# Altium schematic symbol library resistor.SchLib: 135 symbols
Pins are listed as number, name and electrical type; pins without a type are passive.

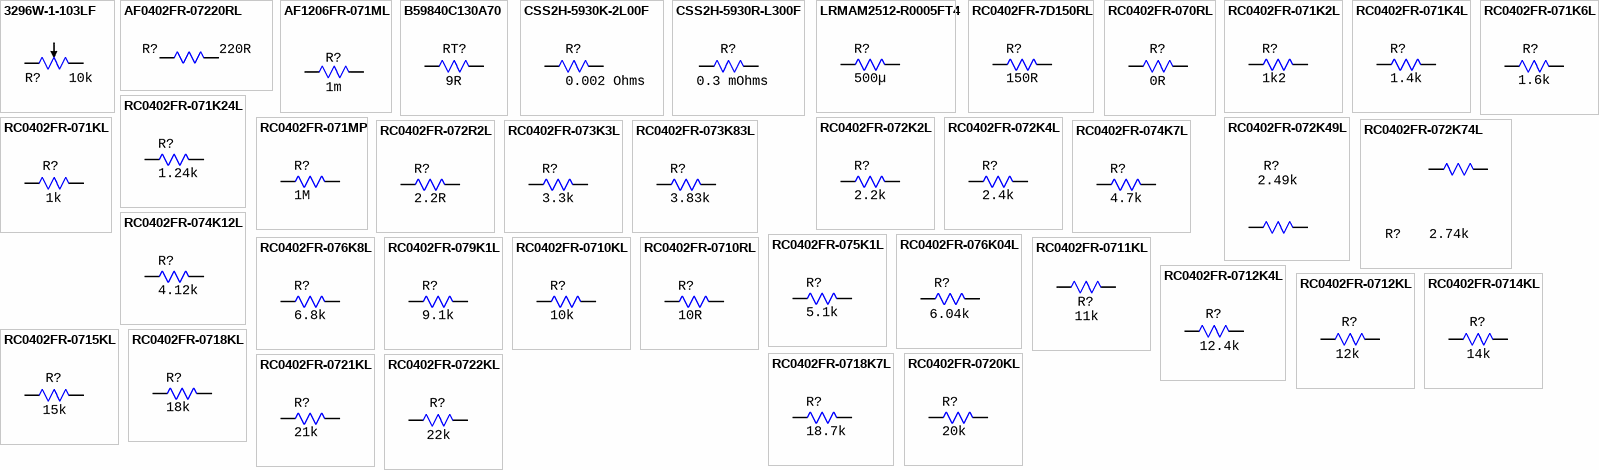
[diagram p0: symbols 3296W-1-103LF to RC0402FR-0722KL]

## 3296W-1-103LF
designator R?  value 10k  (hidden comment: 3296W-1-103LF)
10 kOhms, trimmer, ±10%, 0.5W, -55...+150°C; Manufacturer: Bourns
footprint RES: 3296W
pins: 1, 2, 3

## AF0402FR-07220RL
designator R?  value 220R  (hidden comment: AF0402FR-07220RL)
220 Ohms, 0402, ±1%, 0.062W, -55...+155°C; Manufacturer: YAGEO
footprint RES: 0402
pins: 1, 2

## AF1206FR-071ML
designator R?  value 1m  (hidden comment: AF1206FR-071ML)
1 mOhm, 1206, ±1%, 0.25W, -55...+155°C; Manufacturer: YAGEO
footprint RES: 1206
pins: 1, 2

## B59840C130A70
designator RT?  value 9R  (hidden comment: B59840C130A70)
9 Ohm, 13.5W, 500mA, 265V, D13.5W5H17, -55...+155°C; Manufacturer: Epcos; Manufacturer: TDK EPCOS
footprint RES: B59840C0130A070 (NTC)
pins: 1, 2

## CSS2H-5930K-2L00F
designator R?  value 0.002 Ohms  (hidden comment: CSS2H-5930K-2L00F)
0.002 Ohms, 2512, ±1%, 7W, -55...+170°C; Manufacturer: Bourns
footprint RES: CSS2H (2512)
pins: 1, 2

## CSS2H-5930R-L300F
designator R?  value 0.3 mOhms  (hidden comment: CSS2H-5930R-L300F)
0.0003 Ohms, 2512, ±1%, 10W, -55...+170°C; Manufacturer: Bourns
footprint RES: CSS2H (2512)
pins: 1, 2

## LRMAM2512-R0005FT4
designator R?  value 500µ  (hidden comment: LRMAM2512-R0005FT4)
0.5 mOhms, 2512, ±1%, 2W, -55...+170°C; Manufacturer: Welwyn; Manufacturer: TT Welwyn
footprint RES: CSS2H (2512)
pins: 1, 2

## RC0402FR-7D150RL
designator R?  value 150R  (hidden comment: RC0402FR-7D150RL)
150 Ohms, 0402, ±1%, 0.062W, -55...+155°C; Manufacturer: YAGEO
footprint RES: 0402
pins: 1, 2

## RC0402FR-070RL
designator R?  value 0R  (hidden comment: RC0402FR-070RL)
0 Ohms, 0402, ±1%, 0.062W, -55...+155°C; Manufacturer: Yageo
footprint RES: 0402
pins: 1, 2

## RC0402FR-071K2L
designator R?  value 1k2  (hidden comment: RC0402FR-071K2L)
1.2 kOhm, 0402, ±1%, 0.062W, -55...+155°C; Manufacturer: Yageo
footprint RES: 0402
pins: 1, 2

## RC0402FR-071K4L
designator R?  value 1.4k  (hidden comment: RC0402FR-071K4L)
1.4 kOhm, 0402, ±1%, 0.062W, -55...+155°C; Manufacturer: Yageo
footprint RES: 0402
pins: 1, 2

## RC0402FR-071K6L
designator R?  value 1.6k  (hidden comment: RC0402FR-071K6L)
1.6 kOhms, 0402, ±1%, 0.062W, -55...+155°C; Manufacturer: Yageo
footprint RES: 0402
pins: 1, 2

## RC0402FR-071K24L
designator R?  value 1.24k  (hidden comment: RC0402FR-071K24L)
1.24 kOhm, 0402, ±1%, 0.062W, -55...+155°C; Manufacturer: Yageo
footprint RES: 0402
pins: 1, 2

## RC0402FR-071KL
designator R?  value 1k  (hidden comment: RC0402FR-071KL)
1 kOhm, 0402, ±1%, 0.062W, -55...+155°C; Manufacturer: Yageo
footprint RES: 0402
pins: 1, 2

## RC0402FR-071MP
designator R?  value 1M  (hidden comment: RC0402FR-071MP)
1 MOhms, 0402, ±1%, 0.062W, -55...+155°C; Manufacturer: Yageo; PartNumber: RC0402FR-0793K1L
footprint RES: 0402
pins: 1, 2

## RC0402FR-072K2L
designator R?  value 2.2k  (hidden comment: RC0402FR-072K2L)
2.2 kOhm, 0402, ±1%, 0.062W, -55...+155°C; Manufacturer: Yageo
footprint RES: 0402
pins: 1, 2

## RC0402FR-072K4L
designator R?  value 2.4k  (hidden comment: RC0402FR-072K4L)
2.4 kOhm, 0402, ±1%, 0.062W, -55...+155°C; Manufacturer: Yageo
footprint RES: 0402
pins: 1, 2

## RC0402FR-072K49L
designator R?  value 2.49k  (hidden comment: RC0402FR-072K49L)
2.49 kOhm, 0402, ±1%, 0.062W, -55...+155°C; Manufacturer: Yageo
footprint RES: 0402
pins: 1, 2

## RC0402FR-072K74L
designator R?  value 2.74k  (hidden comment: RC0402FR-072K74L)
2.74 kOhm, 0402, ±1%, 0.062W, -55...+155°C; Manufacturer: Yageo
footprint RES: 0402
pins: 1, 2

## RC0402FR-072R2L
designator R?  value 2.2R  (hidden comment: RC0402FR-072R2L)
2.2 Ohms, 0402, ±1%, 0.062W, -55...+155°C; Manufacturer: YAGEO
footprint RES: 0402
pins: 1, 2

## RC0402FR-073K3L
designator R?  value 3.3k  (hidden comment: RC0402FR-073K3L)
3.3 kOhms, 0402, ±1%, 0.062W, -55...+155°C; Manufacturer: Yageo
footprint RES: 0402
pins: 1, 2

## RC0402FR-073K83L
designator R?  value 3.83k  (hidden comment: RC0402FR-073K83L)
3.83 kOhms, 0402, ±1%, 0.062W, -55...+155°C; Manufacturer: Yageo
footprint RES: 0402
pins: 1, 2

## RC0402FR-074K7L
designator R?  value 4.7k  (hidden comment: RC0402FR-074K7L)
4.7 kOhms, 0402, ±1%, 0.062W, -55...+155°C; Manufacturer: Yageo
footprint RES: 0402
pins: 1, 2

## RC0402FR-074K12L
designator R?  value 4.12k  (hidden comment: RC0402FR-074K12L)
4.12 kOhms, 0402, ±1%, 0.062W, -55...+155°C; Manufacturer: Yageo
footprint RES: 0402
pins: 1, 2

## RC0402FR-075K1L
designator R?  value 5.1k  (hidden comment: RC0402FR-075K1L)
5.1 kOhms, 0402, ±1%, 0.062W, -55...+155°C; Manufacturer: Yageo
footprint RES: 0402
pins: 1, 2

## RC0402FR-076K04L
designator R?  value 6.04k  (hidden comment: RC0402FR-076K04L)
6.04 kOhm, 0402, ±1%, 0.062W, -55...+155°C; Manufacturer: Yageo
footprint RES: 0402
pins: 1, 2

## RC0402FR-076K8L
designator R?  value 6.8k  (hidden comment: RC0402FR-076K8L)
6.8 kOhm, 0402, ±1%, 0.062W, -55...+155°C; Manufacturer: Yageo
footprint RES: 0402
pins: 1, 2

## RC0402FR-079K1L
designator R?  value 9.1k  (hidden comment: RC0402FR-079K1L)
9.1 kOhms, 0402, ±1%, 0.062W, -55...+155°C; Manufacturer: Yageo
footprint RES: 0402
pins: 1, 2

## RC0402FR-0710KL
designator R?  value 10k  (hidden comment: RC0402FR-0710KL)
10 kOhms, 0402, ±1%, 0.062W, -55...+155°C; Manufacturer: Yageo
footprint RES: 0402
pins: 1, 2

## RC0402FR-0710RL
designator R?  value 10R  (hidden comment: RC0402FR-0710RL)
10 Ohms, 0402, ±1%, 0.062W, -55...+155°C; Manufacturer: Yageo
footprint RES: 0402
pins: 1, 2

## RC0402FR-0711KL
designator R?  value 11k  (hidden comment: RC0402FR-0711KL)
11 kOhms, 0402, ±1%, 0.062W, -55...+155°C; Manufacturer: Yageo
footprint RES: 0402
pins: 1, 2

## RC0402FR-0712K4L
designator R?  value 12.4k  (hidden comment: RC0402FR-0712K4L)
12.4 kOhms, 0402, ±1%, 0.062W, -55...+155°C; Manufacturer: Yageo
footprint RES: 0402
pins: 1, 2

## RC0402FR-0712KL
designator R?  value 12k  (hidden comment: RC0402FR-0712KL)
12 kOhms, 0402, ±1%, 0.062W, -55...+155°C; Manufacturer: Yageo
footprint RES: 0402
pins: 1, 2

## RC0402FR-0714KL
designator R?  value 14k  (hidden comment: RC0402FR-0714KL)
14 kOhms, 0402, ±1%, 0.062W, -55...+155°C; Manufacturer: Yageo
footprint RES: 0402
pins: 1, 2

## RC0402FR-0715KL
designator R?  value 15k  (hidden comment: RC0402FR-0715KL)
15 kOhms, 0402, ±1%, 0.062W, -55...+155°C; Manufacturer: Yageo
footprint RES: 0402
pins: 1, 2

## RC0402FR-0718K7L
designator R?  value 18.7k  (hidden comment: RC0402FR-0718K7L)
18.7 kOhm, 0402, ±1%, 0.062W, -55...+155°C; Manufacturer: Yageo
footprint RES: 0402
pins: 1, 2

## RC0402FR-0718KL
designator R?  value 18k  (hidden comment: RC0402FR-0718KL)
18 kOhm, 0402, ±1%, 0.062W, -55...+155°C; Manufacturer: Yageo
footprint RES: 0402
pins: 1, 2

## RC0402FR-0720KL
designator R?  value 20k  (hidden comment: RC0402FR-0720KL)
20 kOhms, 0402, ±1%, 0.062W, -55...+155°C; Manufacturer: Yageo
footprint RES: 0402
pins: 1, 2

## RC0402FR-0721KL
designator R?  value 21k  (hidden comment: RC0402FR-0721KL)
21 kOhms, 0402, ±1%, 0.062W, -55...+155°C; Manufacturer: Yageo
footprint RES: 0402
pins: 1, 2

## RC0402FR-0722KL
designator R?  value 22k  (hidden comment: RC0402FR-0722KL)
22 kOhm, 0402, ±1%, 0.062W, -55...+155°C; Manufacturer: Yageo
footprint RES: 0402
pins: 1, 2

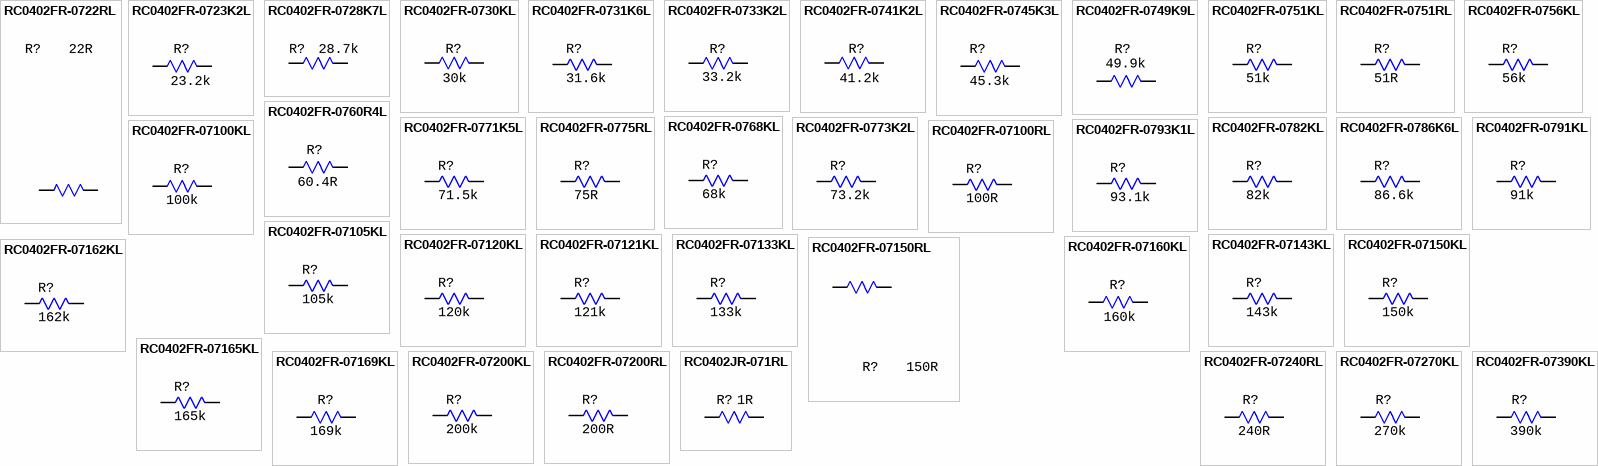
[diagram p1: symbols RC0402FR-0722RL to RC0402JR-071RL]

## RC0402FR-0722RL
designator R?  value 22R  (hidden comment: RC0402FR-0722RL)
22 Ohms, 0402, ±1%, 0.062W, -55...+155°C; Manufacturer: Yageo
footprint RES: 0402
pins: 1, 2

## RC0402FR-0723K2L
designator R?  value 23.2k  (hidden comment: RC0402FR-0723K2L)
23.2 kOhm, 0402, ±1%, 0.062W, -55...+155°C; Manufacturer: Yageo
footprint RES: 0402
pins: 1, 2

## RC0402FR-0728K7L
designator R?  value 28.7k  (hidden comment: RC0402FR-0728K7L)
28.7 kOhms, 0402, ±1%, 0.062W, -55...+155°C; Manufacturer: Yageo
footprint RES: 0402
pins: 1, 2

## RC0402FR-0730KL
designator R?  value 30k  (hidden comment: RC0402FR-0730KL)
30 kOhms, 0402, ±1%, 0.062W, -55...+155°C; Manufacturer: Yageo
footprint RES: 0402
pins: 1, 2

## RC0402FR-0731K6L
designator R?  value 31.6k  (hidden comment: RC0402FR-0731K6L)
31.6 kOhms, 0402, ±1%, 0.062W, -55...+155°C; Manufacturer: Yageo
footprint RES: 0402
pins: 1, 2

## RC0402FR-0733K2L
designator R?  value 33.2k  (hidden comment: RC0402FR-0733K2L)
33.2 kOhms, 0402, ±1%, 0.062W, -55...+155°C; Manufacturer: Yageo
footprint RES: 0402
pins: 1, 2

## RC0402FR-0741K2L
designator R?  value 41.2k  (hidden comment: RC0402FR-0741K2L)
41.2 kOhms, 0402, ±1%, 0.062W, -55...+155°C; Manufacturer: Yageo
footprint RES: 0402
pins: 1, 2

## RC0402FR-0745K3L
designator R?  value 45.3k  (hidden comment: RC0402FR-0745K3L)
45.3 kOhms, 0402, ±1%, 0.062W, -55...+155°C; Manufacturer: Yageo
footprint RES: 0402
pins: 1, 2

## RC0402FR-0749K9L
designator R?  value 49.9k  (hidden comment: RC0402FR-0749K9L)
49.9 kOhm, 0402, ±1%, 0.062W, -55...+155°C; Manufacturer: Yageo
footprint RES: 0402
pins: 1, 2

## RC0402FR-0751KL
designator R?  value 51k  (hidden comment: RC0402FR-0751KL)
51 kOhms, 0402, ±1%, 0.062W, -55...+155°C; Manufacturer: Yageo
footprint RES: 0402
pins: 1, 2

## RC0402FR-0751RL
designator R?  value 51R  (hidden comment: RC0402FR-0751RL)
51 Ohms, 0402, ±1%, 0.062W, -55...+155°C; Manufacturer: Yageo
footprint RES: 0402
pins: 1, 2

## RC0402FR-0756KL
designator R?  value 56k  (hidden comment: RC0402FR-0756KL)
56 kOhms, 0402, ±1%, 0.062W, -55...+155°C; Manufacturer: Yageo
footprint RES: 0402
pins: 1, 2

## RC0402FR-0760R4L
designator R?  value 60.4R  (hidden comment: RC0402FR-0760R4L)
60.4 Ohm, 0402, ±1%, 0.062W, -55...+155°C; Manufacturer: Yageo
footprint RES: 0402
pins: 1, 2

## RC0402FR-0768KL
designator R?  value 68k  (hidden comment: RC0402FR-0768KL)
68 kOhm, 0402, ±1%, 0.062W, -55...+155°C; Manufacturer: Yageo
footprint RES: 0402
pins: 1, 2

## RC0402FR-0771K5L
designator R?  value 71.5k  (hidden comment: RC0402FR-0771K5L)
71.5 kOhm, 0402, ±1%, 0.062W, -55...+155°C; Manufacturer: Yageo
footprint RES: 0402
pins: 1, 2

## RC0402FR-0773K2L
designator R?  value 73.2k  (hidden comment: RC0402FR-0773K2L)
73.2 kOhm, 0402, ±1%, 0.062W, -55...+155°C; Manufacturer: Yageo
footprint RES: 0402
pins: 1, 2

## RC0402FR-0775RL
designator R?  value 75R  (hidden comment: RC0402FR-0775RL)
75 Ohms, 0402, ±1%, 0.062W, -55...+155°C; Manufacturer: Yageo
footprint RES: 0402
pins: 1, 2

## RC0402FR-0782KL
designator R?  value 82k  (hidden comment: RC0402FR-0782KL)
82 kOhms, 0402, ±1%, 0.062W, -55...+155°C; Manufacturer: Yageo
footprint RES: 0402
pins: 1, 2

## RC0402FR-0786K6L
designator R?  value 86.6k  (hidden comment: RC0402FR-0786K6L)
86.6 kOhms, 0402, ±1%, 0.062W, -55...+155°C; Manufacturer: Yageo
footprint RES: 0402
pins: 1, 2

## RC0402FR-0791KL
designator R?  value 91k  (hidden comment: RC0402FR-0791KL)
91 kOhms, 0402, ±1%, 0.062W, -55...+155°C; Manufacturer: Yageo
footprint RES: 0402
pins: 1, 2

## RC0402FR-0793K1L
designator R?  value 93.1k  (hidden comment: RC0402FR-0793K1L)
93.1 kOhm, 0402, ±1%, 0.062W, -55...+155°C; Manufacturer: Yageo
footprint RES: 0402
pins: 1, 2

## RC0402FR-07100KL
designator R?  value 100k  (hidden comment: RC0402FR-07100KL)
100 kOhms, 0402, ±1%, 0.062W, -55...+155°C; Manufacturer: YAGEO
footprint RES: 0402
pins: 1, 2

## RC0402FR-07100RL
designator R?  value 100R  (hidden comment: RC0402FR-07100RL)
100 Ohms, 0402, ±1%, 0.062W, -55...+155°C; Manufacturer: Yageo; Manufacturer Part Number: RC0402FR-13100RL
footprint RES: 0402
pins: 1, 2

## RC0402FR-07105KL
designator R?  value 105k  (hidden comment: RC0402FR-07105KL)
105 kOhm, 0402, ±1%, 0.062W, -55...+155°C; Manufacturer: Yageo
footprint RES: 0402
pins: 1, 2

## RC0402FR-07120KL
designator R?  value 120k  (hidden comment: RC0402FR-07120KL)
120 kOhms, 0402, ±1%, 0.062W, -55...+155°C; Manufacturer: Yageo
footprint RES: 0402
pins: 1, 2

## RC0402FR-07121KL
designator R?  value 121k  (hidden comment: RC0402FR-07121KL)
121 kOhms, 0402, ±1%, 0.062W, -55...+155°C; Manufacturer: Yageo
footprint RES: 0402
pins: 1, 2

## RC0402FR-07133KL
designator R?  value 133k  (hidden comment: RC0402FR-07133KL)
133 kOhm, 0402, ±1%, 0.062W, -55...+155°C; Manufacturer: Yageo
footprint RES: 0402
pins: 1, 2

## RC0402FR-07143KL
designator R?  value 143k  (hidden comment: RC0402FR-07143KL)
143 kOhm, 0402, ±1%, 0.062W, -55...+155°C; Manufacturer: Yageo
footprint RES: 0402
pins: 1, 2

## RC0402FR-07150KL
designator R?  value 150k  (hidden comment: RC0402FR-07150KL)
150 kOhm, 0402, ±1%, 0.062W, -55...+155°C; Manufacturer: Yageo
footprint RES: 0402
pins: 1, 2

## RC0402FR-07150RL
designator R?  value 150R  (hidden comment: RC0402FR-07150RL)
150 Ohms, 0402, ±1%, 0.062W, -55...+155°C; Manufacturer: Yageo; Manufacturer Part Number: RC0402FR-7D150RL
footprint RES: 0402
pins: 1, 2

## RC0402FR-07160KL
designator R?  value 160k  (hidden comment: RC0402FR-07160KL)
160 kOhm, 0402, ±1%, 0.062W, -55...+155°C; Manufacturer: Yageo
footprint RES: 0402
pins: 1, 2

## RC0402FR-07162KL
designator R?  value 162k  (hidden comment: RC0402FR-07162KL)
162 kOhm, 0402, ±1%, 0.062W, -55...+155°C; Manufacturer: Yageo
footprint RES: 0402
pins: 1, 2

## RC0402FR-07165KL
designator R?  value 165k  (hidden comment: RC0402FR-07165KL)
165 kOhm, 0402, ±1%, 0.062W, -55...+155°C; Manufacturer: Yageo
footprint RES: 0402
pins: 1, 2

## RC0402FR-07169KL
designator R?  value 169k  (hidden comment: RC0402FR-07169KL)
169 kOhm, 0402, ±1%, 0.062W, -55...+155°C; Manufacturer: Yageo
footprint RES: 0402
pins: 1, 2

## RC0402FR-07200KL
designator R?  value 200k  (hidden comment: RC0402FR-07200KL)
200 kOhms, 0402, ±1%, 0.062W, -55...+155°C; Manufacturer: Yageo
footprint RES: 0402
pins: 1, 2

## RC0402FR-07200RL
designator R?  value 200R  (hidden comment: RC0402FR-07200RL)
200 Ohms, 0402, ±1%, 0.062W, -55...+155°C; Manufacturer: Yageo
footprint RES: 0402
pins: 1, 2

## RC0402FR-07240RL
designator R?  value 240R  (hidden comment: RC0402FR-07240RL)
240 Ohms, 0402, ±1%, 0.062W, -55...+155°C; Manufacturer: Yageo
footprint RES: 0402
pins: 1, 2

## RC0402FR-07270KL
designator R?  value 270k  (hidden comment: RC0402FR-07270KL)
270 kOhm, 0402, ±1%, 0.062W, -55...+155°C; Manufacturer: Yageo
footprint RES: 0402
pins: 1, 2

## RC0402FR-07390KL
designator R?  value 390k  (hidden comment: RC0402FR-07390KL)
390 kOhm, 0402, ±1%, 0.062W, -55...+155°C; Manufacturer: Yageo
footprint RES: 0402
pins: 1, 2

## RC0402JR-071RL
designator R?  value 1R  (hidden comment: RC0402JR-071RL)
1 Ohms, 0402, ±5%, 0.062W, -55...+155°C; Manufacturer: Yageo
footprint RES: 0402
pins: 1, 2

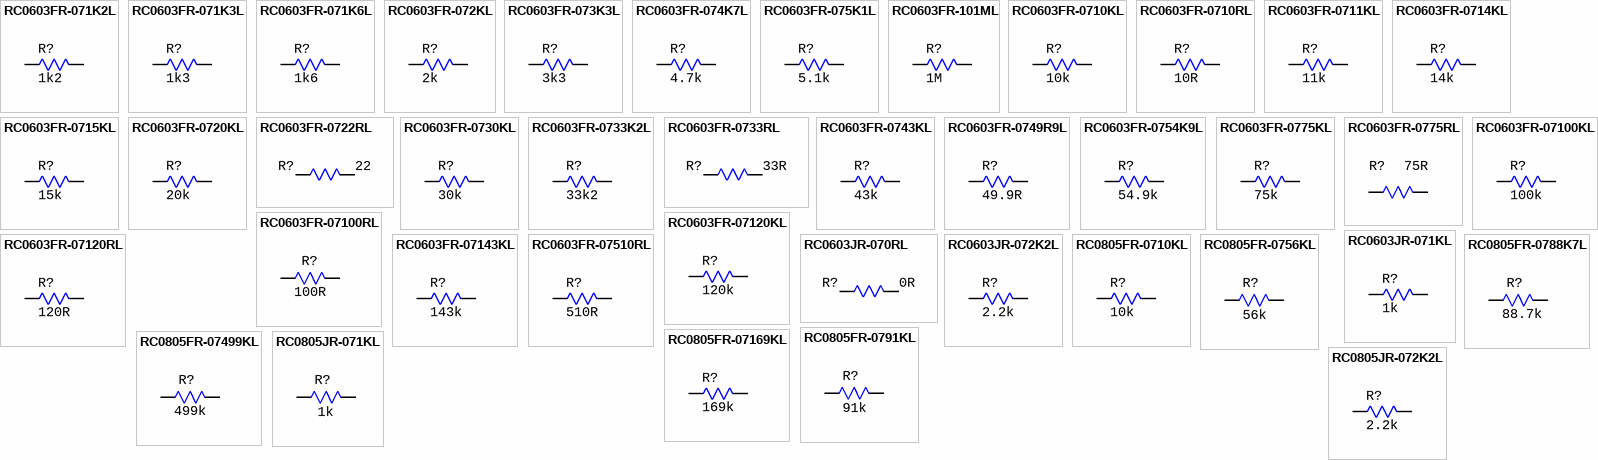
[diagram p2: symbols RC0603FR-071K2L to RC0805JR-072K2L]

## RC0603FR-071K2L
designator R?  value 1k2  (hidden comment: RC0603FR-071K2L)
1.2 kOhms, 0603, ±1%, 0.1W, -55...+155°C; Manufacturer: Yageo
footprint RES: 0603
pins: 1, 2

## RC0603FR-071K3L
designator R?  value 1k3  (hidden comment: RC0603FR-071K3L)
1.3 kOhms, 0603, ±1%, 0.1W, -55...+155°C; Manufacturer: Yageo
footprint RES: 0603
pins: 1, 2

## RC0603FR-071K6L
designator R?  value 1k6  (hidden comment: RC0603FR-071K6L)
1.6 kOhms, 0603, ±1%, 0.1W, -55...+155°C; Manufacturer: Yageo
footprint RES: 0603
pins: 1, 2

## RC0603FR-072KL
designator R?  value 2k  (hidden comment: RC0603FR-072KL)
2 kOhms, 0603, ±1%, 0.1W, -55...+155°C; Manufacturer: Yageo
footprint RES: 0603
pins: 1, 2

## RC0603FR-073K3L
designator R?  value 3k3  (hidden comment: RC0603FR-073K3L)
3.3 kOhms, 0603, ±1%, 0.1W, -55...+155°C; Manufacturer: Yageo
footprint RES: 0603
pins: 1, 2

## RC0603FR-074K7L
designator R?  value 4.7k  (hidden comment: RC0603FR-074K7L)
4.7 kOhms, 0603, ±1%, 0.1W, -55...+155°C; Manufacturer: YAGEO
footprint RES: 0603
pins: 1, 2

## RC0603FR-075K1L
designator R?  value 5.1k  (hidden comment: RC0603FR-075K1L)
5.1 kOhms, 0603, ±1%, 0.1W, -55...+155°C; Manufacturer: Yageo
footprint RES: 0603
pins: 1, 2

## RC0603FR-101ML
designator R?  value 1M  (hidden comment: RC0603FR-101ML)
1 MOhm, 0603, ±1%, 0.1W, -55...+155°C; Manufacturer: YAGEO
footprint RES: 0603
pins: 1, 2

## RC0603FR-0710KL
designator R?  value 10k  (hidden comment: RC0603FR-0710KL)
10 kOhms, 0603, ±1%, 0.1W, -55...+155°C; Manufacturer: Yageo
footprint RES: 0603
pins: 1, 2

## RC0603FR-0710RL
designator R?  value 10R  (hidden comment: RC0603FR-0710RL)
10 Ohms, 0603, ±1%, 0.1W, -55...+155°C; Manufacturer: YAGEO
footprint RES: 0603
pins: 1, 2

## RC0603FR-0711KL
designator R?  value 11k  (hidden comment: RC0603FR-0711KL)
11 kOhms, 0603, ±1%, 0.1W, -55...+155°C; Manufacturer: Yageo
footprint RES: 0603
pins: 1, 2

## RC0603FR-0714KL
designator R?  value 14k  (hidden comment: RC0603FR-0714KL)
14 kOhms, 0603, ±1%, 0.1W, -55...+155°C; Manufacturer: Yageo
footprint RES: 0603
pins: 1, 2

## RC0603FR-0715KL
designator R?  value 15k  (hidden comment: RC0603FR-0715KL)
15 kOhms, 0603, ±1%, 0.1W, -55...+155°C; Manufacturer: Yageo
footprint RES: 0603
pins: 1, 2

## RC0603FR-0720KL
designator R?  value 20k  (hidden comment: RC0603FR-0720KL)
20 kOhms, 0603, ±1%, 0.1W, -55...+155°C; Manufacturer: Yageo
footprint RES: 0603
pins: 1, 2

## RC0603FR-0722RL
designator R?  value 22  (hidden comment: RC0603FR-0722RL)
22 Ohms, 0603, ±1%, 0.1W, -55...+155°C; Manufacturer: YAGEO
footprint RES: 0603
pins: 1, 2

## RC0603FR-0730KL
designator R?  value 30k  (hidden comment: RC0603FR-0730KL)
30 kOhms, 0603, ±1%, 0.1W, -55...+155°C; Manufacturer: Yageo
footprint RES: 0603
pins: 1, 2

## RC0603FR-0733K2L
designator R?  value 33k2  (hidden comment: RC0603FR-0733K2L)
33.2 kOhms, 0603, ±1%, 0.1W, -55...+155°C; Manufacturer: Yageo
footprint RES: 0603
pins: 1, 2

## RC0603FR-0733RL
designator R?  value 33R  (hidden comment: RC0603FR-0733RL)
33 Ohms, 0603, ±1%, 0.1W, -55...+155°C; Manufacturer: YAGEO
footprint RES: 0603
pins: 1, 2

## RC0603FR-0743KL
designator R?  value 43k  (hidden comment: RC0603FR-0743KL)
43 kOhms, 0603, ±1%, 0.1W, -55...+155°C; Manufacturer: Yageo
footprint RES: 0603
pins: 1, 2

## RC0603FR-0749R9L
designator R?  value 49.9R  (hidden comment: RC0603FR-0749R9L)
49.9 Ohms, 0603, ±1%, 0.1W, -55...+155°C; Manufacturer: YAGEO
footprint RES: 0603
pins: 1, 2

## RC0603FR-0754K9L
designator R?  value 54.9k  (hidden comment: RC0603FR-0754K9L)
54.9 kOhms, 0603, ±1%, 0.1W, -55...+155°C; Manufacturer: Yageo
footprint RES: 0603
pins: 1, 2

## RC0603FR-0775KL
designator R?  value 75k  (hidden comment: RC0603FR-0775KL)
75 kOhms, 0603, ±1%, 0.1W, -55...+155°C; Manufacturer: Yageo
footprint RES: 0603
pins: 1, 2

## RC0603FR-0775RL
designator R?  value 75R  (hidden comment: RC0603FR-0775RL)
75 Ohms, 0603, ±1%, 0.1W, -55...+155°C; Manufacturer: Yageo
footprint RES: 0603
pins: 1, 2

## RC0603FR-07100KL
designator R?  value 100k  (hidden comment: RC0603FR-07100KL)
100 kOhms, 0603, ±1%, 0.1W, -55...+155°C; Manufacturer: Yageo
footprint RES: 0603
pins: 1, 2

## RC0603FR-07100RL
designator R?  value 100R  (hidden comment: RC0603FR-07100RL)
100 Ohms, 0603, ±1%, 0.1W, -55...+155°C; Manufacturer: Yageo
footprint RES: 0603
pins: 1, 2

## RC0603FR-07120KL
designator R?  value 120k  (hidden comment: RC0603FR-07120KL)
120 kOhms, 0603, ±1%, 0.062W, -55...+155°C; Manufacturer: Yageo
footprint RES: 0603
pins: 1, 2

## RC0603FR-07120RL
designator R?  value 120R  (hidden comment: RC0603FR-07120RL)
120 Ohms, 0603, ±1%, 0.062W, -55...+155°C; Manufacturer: Yageo
footprint RES: 0603
pins: 1, 2

## RC0603FR-07143KL
designator R?  value 143k  (hidden comment: RC0603FR-07143KL)
143 kOhms, 0603, ±1%, 0.1W, -55...+155°C; Manufacturer: Yageo
footprint RES: 0603
pins: 1, 2

## RC0603FR-07510RL
designator R?  value 510R  (hidden comment: RC0603FR-07510RL)
510 Ohms, 0603, ±1%, 0.1W, -55...+155°C; Manufacturer: YAGEO
footprint RES: 0603
pins: 1, 2

## RC0603JR-070RL
designator R?  value 0R  (hidden comment: RC0603JR-070RL)
0 Ohms, 0603, ±5%, 0.1W, -55...+155°C; Manufacturer: Yageo
footprint RES: 0603
pins: 1, 2

## RC0603JR-071KL
designator R?  value 1k  (hidden comment: RC0603JR-071KL)
1 kOhms, 0603, ±5%, 0.1W, -55...+155°C; Manufacturer: Yageo
footprint RES: 0603
pins: 1, 2

## RC0603JR-072K2L
designator R?  value 2.2k  (hidden comment: RC0603JR-072K2L)
2.2 kOhms, 0603, ±5%, 0.1W, -55...+155°C; Manufacturer: Yageo
footprint RES: 0603
pins: 1, 2

## RC0805FR-0710KL
designator R?  value 10k  (hidden comment: RC0805FR-0710KL)
10 kOhms, 0805, ±1%, 0.125W, -55...+155°C; Manufacturer: Yageo
footprint RES: 0805
pins: 1, 2

## RC0805FR-0756KL
designator R?  value 56k  (hidden comment: RC0805FR-0756KL)
56 kOhms, 0805, ±1%, 0.125W, -55...+155°C; Manufacturer: Yageo
footprint RES: 0805
pins: 1, 2

## RC0805FR-0788K7L
designator R?  value 88.7k  (hidden comment: RC0805FR-0788K7L)
88.7 kOhms, 0805, ±1%, 0.125W, -55...+155°C; Manufacturer: Yageo
footprint RES: 0805
pins: 1, 2

## RC0805FR-0791KL
designator R?  value 91k  (hidden comment: RC0805FR-0791KL)
91 kOhms, 0805, ±1%, 0.125W, -55...+155°C; Manufacturer: Yageo
footprint RES: 0805
pins: 1, 2

## RC0805FR-07169KL
designator R?  value 169k  (hidden comment: RC0805FR-07169KL)
169 kOhms, 0805, ±1%, 0.125W, -55...+155°C; Manufacturer: Yageo
footprint RES: 0805
pins: 1, 2

## RC0805FR-07499KL
designator R?  value 499k  (hidden comment: RC0805FR-07499KL)
88.7 kOhms, 0805, ±1%, 0.125W, -55...+155°C; Manufacturer: Yageo
footprint RES: 0805
pins: 1, 2

## RC0805JR-071KL
designator R?  value 1k  (hidden comment: RC0805JR-071KL)
1 kOhms, 0805, ±5%, 0.125W, -55...+155°C; Manufacturer: Yageo
footprint RES: 0805
pins: 1, 2

## RC0805JR-072K2L
designator R?  value 2.2k  (hidden comment: RC0805JR-072K2L)
2.2 kOhms, 0805, ±5%, 0.125W, -55...+155°C; Manufacturer: Yageo; Manufacturer Part Number: RC0805JR-07100RL
footprint RES: 0805
pins: 1, 2

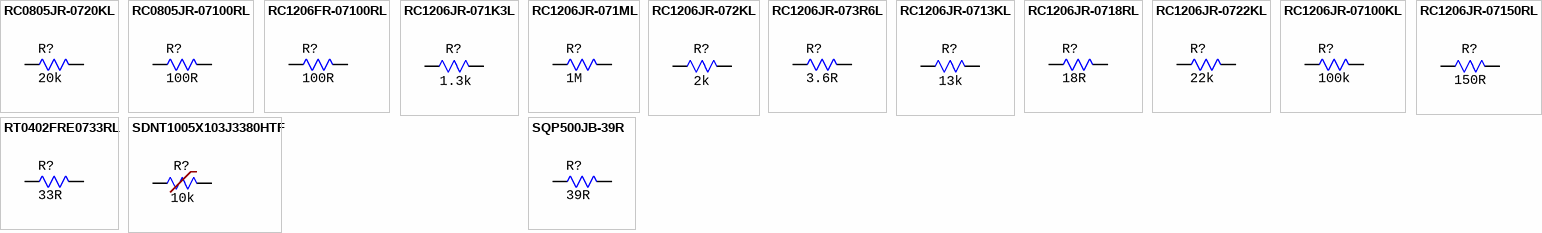
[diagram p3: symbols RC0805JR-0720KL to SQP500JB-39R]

## RC0805JR-0720KL
designator R?  value 20k  (hidden comment: RC0805JR-0720KL)
20 kOhms, 0805, ±5%, 0.125W, -55...+155°C; Manufacturer: Yageo
footprint RES: 0805
pins: 1, 2

## RC0805JR-07100RL
designator R?  value 100R  (hidden comment: RC0805JR-07100RL)
100 Ohms, 0805, ±5%, 0.125W, -55...+155°C; Manufacturer: Yageo
footprint RES: 0805
pins: 1, 2

## RC1206FR-07100RL
designator R?  value 100R  (hidden comment: RC1206FR-07100RL)
100 Ohms, 1206, ±1%, 0.25W, -55...+155°C; Manufacturer: Yageo
footprint RES: 1206
pins: 1, 2

## RC1206JR-071K3L
designator R?  value 1.3k  (hidden comment: RC1206JR-071K3L)
1.3 kOhms, 1206, ±5%, 0.25W, -55...+155°C; Manufacturer: Yageo
footprint RES: 1206
pins: 1, 2

## RC1206JR-071ML
designator R?  value 1M  (hidden comment: RC1206JR-071ML)
1 MOhms, 1206, ±5%, 0.25W, -55...+155°C; Manufacturer: Yageo
footprint RES: 1206
pins: 1, 2

## RC1206JR-072KL
designator R?  value 2k  (hidden comment: RC1206JR-072KL)
2 kOhms, 1206, ±5%, 0.25W, -55...+155°C; Manufacturer: Yageo
footprint RES: 1206
pins: 1, 2

## RC1206JR-073R6L
designator R?  value 3.6R  (hidden comment: RC1206JR-073R6L)
3.6 Ohms, 1206, ±5%, 0.25W, -55...+155°C; Manufacturer: Yageo
footprint RES: 1206
pins: 1, 2

## RC1206JR-0713KL
designator R?  value 13k  (hidden comment: RC1206JR-0713KL)
13 kOhms, 1206, ±5%, 0.25W, -55...+155°C; Manufacturer: Yageo
footprint RES: 1206
pins: 1, 2

## RC1206JR-0718RL
designator R?  value 18R  (hidden comment: RC1206JR-0718RL)
18 Ohms, 1206, ±5%, 0.25W, -55...+155°C; Manufacturer: Yageo
footprint RES: 1206
pins: 1, 2

## RC1206JR-0722KL
designator R?  value 22k  (hidden comment: RC1206JR-0722KL)
22 kOhms, 1206, ±5%, 0.25W, -55...+155°C; Manufacturer: Yageo
footprint RES: 1206
pins: 1, 2

## RC1206JR-07100KL
designator R?  value 100k  (hidden comment: RC1206JR-07100KL)
100 kOhms, 1206, ±5%, 0.25W, -55...+155°C; Manufacturer: Yageo
footprint RES: 1206
pins: 1, 2

## RC1206JR-07150RL
designator R?  value 150R  (hidden comment: RC1206JR-07150RL)
150 Ohms, 1206, ±5%, 0.25W, -55...+155°C; Manufacturer: Yageo
footprint RES: 1206
pins: 1, 2

## RT0402FRE0733RL
designator R?  value 33R  (hidden comment: RT0402FRE0733RL)
33 Ohms, 0402, ±1%, 0.062W, -55...+155°C; Manufacturer: YAGEO
footprint RES: 0402
pins: 1, 2

## SDNT1005X103J3380HTF
designator R?  value 10k  (hidden comment: SDNT1005X103J3380HTF)
10 kOhms, NTC, 0402, ±3%, 3380K, -55...+125°C; Manufacturer: Sunlord
footprint RES: 0402
pins: 1, 2

## SQP500JB-39R
designator R?  value 39R  (hidden comment: SQP500JB-39R)
39R, SQP, ±5%, 5W, -55...+155°C; Manufacturer: Yageo
footprint RES: SQP 5W
pins: 1, 2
